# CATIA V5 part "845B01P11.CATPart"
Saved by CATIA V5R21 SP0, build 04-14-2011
Part number: 845B01P11
Bounding box of the stored display mesh (mm): x -51 to 51, y -25.54 to 25.54, z -6.5 to 6.5
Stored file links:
  C:\Users\ALI OZGUN\Desktop\alhan\845B01P11.CATPart
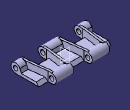
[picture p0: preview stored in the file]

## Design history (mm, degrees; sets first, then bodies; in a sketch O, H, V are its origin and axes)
Body1 (main body)
  Sketch1 on yz-plane, origin (0, 0, 0), H (0, 1, 0), V (0, 0, 1)
    construction line L1 (-19.05, 0) -> (19.05, 0)
    point P1 (-19.05, 0)
    point P2 (19.05, 0)
    line L2 (-19.05, 6.5) -> (19.05, 6.5)
    line L3 (19.05, -6.5) -> (-19.05, -6.5)
    arc A1 centre (19.05, 0) radius 6.5 from (19.05, 6.5) to (19.05, -6.5) cw
    arc A2 centre (-19.05, 0) radius 6.5 from (-19.05, -6.5) to (-19.05, 6.5) cw
    circle A3 centre (19.05, 0) radius 3.25
    circle A4 centre (-19.05, 0) radius 3.25
    distance L1 L2 = 6.5
    length L1 = 38.1
    distance P2 V = 19.05
    radius A3 = 3.25
    radius A4 = 3.25
    coincidence: P1 H
    horizontal: L1 H
    tangency: A1 L2, A2 L2, A1 L3, A2 L3
  Pad1: profile Sketch1, direction (1, 0, 0), length 51, mirrored extent
  Sketch2 on face of Pad1 from Sketch1.L2, origin (0, 0, 6.5), H (1, 0, 0), V (0, 1, 0)
    line L1 (12.5, -14) -> (38.5, -14)
    line L2 (38.5, -14) -> (38.5, -36.0786)
    line L3 (38.5, -36.0786) -> (12.5, -36.0786)
    line L4 (12.5, -36.0786) -> (12.5, -14)
    line L5 (-38.5, -14) -> (-12.5, -14)
    line L6 (-12.5, -14) -> (-12.5, -32.269)
    line L7 (-12.5, -32.269) -> (-38.5, -32.269)
    line L8 (-38.5, -32.269) -> (-38.5, -14)
    line L9 (60.2823, 31.3847) -> (38, 31.3847)
    line L10 (38, 31.3847) -> (38, 14)
    line L11 (38, 14) -> (60.2823, 14)
    line L12 (60.2823, 14) -> (60.2823, 31.3847)
    point P13 (-13, 31.3847)
    line L13 (-13, 31.3847) -> (13, 31.3847)
    line L14 (13, 31.3847) -> (13, 14)
    line L15 (13, 14) -> (-13, 14)
    line L16 (-13, 14) -> (-13, 31.3847)
    point P15 (13, 14)
    line L17 (-55.9786, 33.8185) -> (-38, 33.8185)
    line L18 (-38, 33.8185) -> (-38, 14)
    line L19 (-38, 14) -> (-55.9786, 14)
    line L20 (-55.9786, 14) -> (-55.9786, 33.8185)
    point P19 (-38, 14)
    reference projected line E1 (51, 19.05) -> (51, -19.05) from edge [face of Pad1 from Sketch1.L2 | end face of Pad1]
    reference projected line E2 (-51, 19.05) -> (-51, -19.05) from edge [start face of Pad1 | face of Pad1 from Sketch1.L2]
    reference projected line E3 (-51, 19.05) -> (-51, -19.05) from edge [start face of Pad1 | face of Pad1 from Sketch1.L2]
    reference projected line E4 (51, 19.05) -> (51, -19.05) from edge [face of Pad1 from Sketch1.L2 | end face of Pad1]
    reference projected line E5 through (0, 19.05) direction (1, 0) from axis of face of Pad1 from Sketch1.A1
    reference projected line E6 through (0, -19.05) direction (1, 0) from axis of face of Pad1 from Sketch1.A2
    distance L10 E1 = 13
    distance L18 E2 = 13
    distance L8 E3 = 12.5
    distance L2 E4 = 12.5
    distance L4 L2 = 26
    distance L8 L6 = 26
    distance L14 L10 = 25
    distance L16 L14 = 26
    distance L10 L12 = 22.2823
    distance L18 L20 = 17.9786
    distance L15 E5 = 5.05
    distance L1 E6 = 5.05
    horizontal: L1 H, L3 H, L5 H, L7 H, L9 H, L11 H, L13 H, L15 H, L17 H, L19 H
    vertical: L2 V, L4 V, L6 V, L8 V, L10 V, L12 V, L14 V, L16 V, L18 V, L20 V
    coincidence: P13 L9, P15 L11, P19 L11
  Pocket1: profile Sketch2, direction (0, 0, -1), length 53.5
  Sketch3 on end face of Pad1, origin (51, 0, 0), H (0, 1, 0), V (0, 0, 1)
    projected arc E1 centre (19.05, 0) radius 6.5 from (19.05, -6.5) to (19.05, 6.5) ccw from edge [face of Pocket1 from Sketch2.L10 | face of Pad1 from Sketch1.A1]
    projected arc E2 centre (19.05, 0) radius 6.5 from (19.05, -6.5) to (13.0358, 2.4657) ccw from edge [face of Pocket1 from Sketch2.L10 | face of Pad1 from Sketch1.A1]
    point P1 (19.05, -6.5)
    projected arc E3 centre (-19.05, 0) radius 6.5 from (-19.05, 6.5) to (-19.05, -6.5) ccw from edge [face of Pad1 from Sketch1.A2 | end face of Pad1]
    projected arc E4 centre (-19.05, 0) radius 6.5 from (-13.0358, 2.4657) to (-19.05, -6.5) ccw from edge [face of Pad1 from Sketch1.A2 | end face of Pad1]
    point P4 (-19.05, -6.5)
    projected line E5 (-19.05, -6.5) -> (14, -6.5) from edge [face of Pad1 from Sketch1.L3 | end face of Pad1]
    point P5 (-19.05, -6.5)
    projected line E6 (19.05, -6.5) -> (14, -6.5) from edge [face of Pocket1 from Sketch2.L10 | face of Pad1 from Sketch1.L3]
    point P7 (19.05, -6.5)
    line L1 (-13.0358, 2.4657) -> (-11, -2.5)
    line L2 (-11, -2.5) -> (11, -2.5)
    point P10 (11, -2.5)
    line L3 (11, -2.5) -> (13.0358, 2.4657)
    distance L2 E5 = 4
    length L2 = 22
    distance P10 V = 11
    horizontal: L2 H
    tangency: L3 E1, L1 E3
    coincidence: P1 P7, P4 P5
  Pocket2: profile Sketch3, direction (-1, 0, 0), length 172.5, outer side
  Sketch4 on face of Pocket2 from Sketch3.L2, origin (0, 0, -2.5), H (1, 0, 0), V (0, 1, 0)
    projected line E1 (12.5, -14) -> (12.5, -25.55) from edge [face of Pocket2 | face of Pocket1 from Sketch2.L4]
    projected line E2 (12.5, -14) -> (12.5, -19.05) from edge [face of Pocket2 | face of Pocket1 from Sketch2.L4]
    point P1 (12.5, -14)
    point P2 (12.5, -25.55)
    projected line E3 (38.5, -25.55) -> (38.5, -14) from edge [face of Pocket2 | face of Pocket1 from Sketch2.L2]
    projected line E4 (38.5, -19.05) -> (38.5, -14) from edge [face of Pocket2 | face of Pocket1 from Sketch2.L2]
    point P3 (38.5, -25.55)
    point P4 (38.5, -14)
    projected line E5 (13, 14) -> (13, 25.55) from edge [face of Pocket2 | face of Pocket1 from Sketch2.L14]
    projected line E6 (13, 14) -> (13, 19.05) from edge [face of Pocket2 | face of Pocket1 from Sketch2.L14]
    point P5 (13, 14)
    point P6 (13, 25.55)
    projected line E7 (38, 14) -> (38, 25.55) from edge [face of Pocket1 from Sketch2.L10 | face of Pocket2]
    projected line E8 (38, 14) -> (38, 19.05) from edge [face of Pocket1 from Sketch2.L10 | face of Pocket2]
    point P7 (38, 14)
    point P8 (38, 25.55)
    offset line E9 (9.5, -14) -> (9.5, -25.55) from edge [face of Pocket2 | face of Pocket1 from Sketch2.L4]
    offset line E10 (9.5, -14) -> (9.5, -19.05) from edge [face of Pocket2 | face of Pocket1 from Sketch2.L4]
    point P9 (9.5, -14)
    point P10 (9.5, -25.55)
    offset line E11 (16, 14) -> (16, 25.55) from edge [face of Pocket2 | face of Pocket1 from Sketch2.L14]
    offset line E12 (16, 14) -> (16, 19.05) from edge [face of Pocket2 | face of Pocket1 from Sketch2.L14]
    point P11 (16, 14)
    point P12 (16, 25.55)
    offset line E13 (35, 14) -> (35, 25.55) from edge [face of Pocket1 from Sketch2.L10 | face of Pocket2]
    offset line E14 (35, 14) -> (35, 19.05) from edge [face of Pocket1 from Sketch2.L10 | face of Pocket2]
    point P13 (35, 14)
    point P14 (35, 25.55)
    offset line E15 (41.5, -25.55) -> (41.5, -14) from edge [face of Pocket2 | face of Pocket1 from Sketch2.L2]
    offset line E16 (41.5, -19.05) -> (41.5, -14) from edge [face of Pocket2 | face of Pocket1 from Sketch2.L2]
    point P15 (41.5, -25.55)
    point P16 (41.5, -14)
    line L1 (9.5, -14) -> (13, 14)
    line L2 (12.5, -14) -> (16, 14)
    line L3 (38.5, -14) -> (35, 14)
    line L4 (41.5, -14) -> (38, 14)
    projected line E17 through (0, -19.05) direction (1, 0) from axis of face of Pocket2
    projected line E18 (38.5, -19.05) -> (41.5, -19.05) from axis of face of Pocket2
    projected line E19 (9.5, -19.05) -> (12.5, -19.05) from axis of face of Pocket2
    point P17 (-10000000, -19.05)
    point P18 (10000000, -19.05)
    point P19 (41.5, -19.05)
    point P20 (12.5, -19.05)
    point P21 (38.5, -19.05)
    point P22 (38.5, -19.05)
    point P23 (12.5, -19.05)
    point P24 (9.5, -19.05)
    point P25 (9.5, -19.05)
    projected line E20 through (0, 19.05) direction (1, 0) from axis of face of Pocket2
    projected line E21 (13, 19.05) -> (16, 19.05) from axis of face of Pocket2
    projected line E22 (35, 19.05) -> (38, 19.05) from axis of face of Pocket2
    point P26 (-10000000, 19.05)
    point P27 (10000000, 19.05)
    point P28 (38, 19.05)
    point P29 (13, 19.05)
    point P30 (13, 19.05)
    point P31 (16, 19.05)
    point P32 (35, 19.05)
    point P33 (16, 19.05)
    point P34 (35, 19.05)
    point P35 (-10000000, -19.05)
    point P36 (10000000, -19.05)
    point P37 (-10000000, 19.05)
    point P38 (10000000, 19.05)
    construction line L5 through (0, -19.05) direction (-1, 0)
    construction line L6 through (0, 19.05) direction (-1, 0)
    point P39 (-10000000, -19.05)
    point P40 (10000000, -19.05)
    point P41 (13, 14)
    point P42 (13, 25.55)
    point P43 (16, 14)
    point P44 (16, 25.55)
    point P45 (-10000000, 19.05)
    point P46 (10000000, 19.05)
    construction line L7 through (0, -19.05) direction (-1, 0)
    construction line L8 (13, 25.55) -> (13, 14)
    construction line L9 (16, 25.55) -> (16, 14)
    construction line L10 through (0, 19.05) direction (-1, 0)
    point P47 (-10000000, -19.05)
    point P48 (10000000, -19.05)
    point P49 (-10000000, 19.05)
    point P50 (10000000, 19.05)
    construction line L11 through (0, -19.05) direction (-1, 0)
    construction line L12 through (0, 19.05) direction (-1, 0)
    point P51 (-10000000, -19.05)
    point P52 (10000000, -19.05)
    point P53 (-41.5, -19.05)
    point P54 (-38.5, -19.05)
    point P55 (-12.5, -19.05)
    point P56 (-9.5, -19.05)
    point P57 (-13, 14)
    point P58 (-13, 25.55)
    construction line L13 (-13, 25.55) -> (-13, 14)
    point P59 (-16, 14)
    point P60 (-16, 25.55)
    construction line L14 (-16, 25.55) -> (-16, 14)
    point P61 (-12.5, -25.55)
    point P62 (-12.5, -14)
    point P63 (-12.5, -19.05)
    point P64 (-38.5, -14)
    point P65 (-38.5, -25.55)
    point P66 (-38.5, -19.05)
    point P67 (-13, 25.55)
    point P68 (-13, 14)
    point P69 (-13, 19.05)
    point P70 (-38, 25.55)
    point P71 (-38, 14)
    point P72 (-38, 19.05)
    point P73 (-9.5, -25.55)
    point P74 (-9.5, -14)
    point P75 (-9.5, -19.05)
    point P76 (-16, 25.55)
    point P77 (-16, 14)
    point P78 (-16, 19.05)
    point P79 (-35, 25.55)
    point P80 (-35, 14)
    point P81 (-35, 19.05)
    point P82 (-41.5, -14)
    point P83 (-41.5, -25.55)
    line L15 (-9.5, -14) -> (-13, 14)
    line L16 (-12.5, -14) -> (-16, 14)
    line L17 (-38.5, -14) -> (-35, 14)
    line L18 (-41.5, -14) -> (-38, 14)
    point P84 (-10000000, 19.05)
    point P85 (10000000, 19.05)
    point P86 (-16, 19.05)
    point P87 (-13, 19.05)
    point P88 (-35, 19.05)
    construction line L19 through (0, -19.05) direction (-1, 0)
    line L20 (-38.5, -19.05) -> (-41.5, -19.05)
    line L21 (-9.5, -19.05) -> (-12.5, -19.05)
    construction line L22 (-12.5, -14) -> (-12.5, -25.55)
    line L23 (-12.5, -14) -> (-12.5, -19.05)
    construction line L24 (-38.5, -25.55) -> (-38.5, -14)
    line L25 (-38.5, -19.05) -> (-38.5, -14)
    construction line L26 (-13, 14) -> (-13, 25.55)
    line L27 (-13, 14) -> (-13, 19.05)
    construction line L28 (-38, 14) -> (-38, 25.55)
    line L29 (-38, 14) -> (-38, 19.05)
    construction line L30 (-9.5, -14) -> (-9.5, -25.55)
    line L31 (-9.5, -14) -> (-9.5, -19.05)
    construction line L32 (-16, 14) -> (-16, 25.55)
    line L33 (-16, 14) -> (-16, 19.05)
    construction line L34 (-35, 14) -> (-35, 25.55)
    line L35 (-35, 14) -> (-35, 19.05)
    construction line L36 (-41.5, -25.55) -> (-41.5, -14)
    line L37 (-41.5, -19.05) -> (-41.5, -14)
    construction line L38 through (0, 19.05) direction (-1, 0)
    line L39 (-13, 19.05) -> (-16, 19.05)
    line L40 (-35, 19.05) -> (-38, 19.05)
    parallelism: L2 L1
    coincidence: E1 P20, E3 P21, E17 P22, E17 P23, E17 P24, E9 P25, E5 P29, E20 P30, E20 P31, E20 P32, E11 P33, E13 P34, P21 P22, P24 P25, P29 P30, P31 P33, P32 P34
    symmetry: P18 P35 V, P17 P36 V, E17 L5 V, P27 P37 V, P26 P38 V, E20 L6 V, P18 P39 V, P17 P40 V, E17 L7 V, P27 P45 V, P26 P46 V, E20 L10 V, P18 P47 V, P17 P48 V, E17 L11 V, P27 P49 V, P26 P50 V, E20 L12 V, P18 P51 V, P17 P52 V, P19 P53 V, P21 P54 V, P20 P55 V, P25 P56 V, E17 L19 V, P41 P57 V, P42 P58 V, L8 L13 V, P43 P59 V, P44 P60 V, L9 L14 V, P2 P61 V, P1 P62 V, P23 P63 V, E1 L22 V, P4 P64 V, P3 P65 V, P22 P66 V, E3 L24 V, P6 P67 V, P5 P68 V, P30 P69 V, E5 L26 V, P8 P70 V, P7 P71 V, P28 P72 V, E7 L28 V, P10 P73 V, P9 P74 V, P24 P75 V, E9 L30 V, P12 P76 V, P11 P77 V, P31 P78 V, E11 L32 V, P14 P79 V, P13 P80 V, P32 P81 V, E13 L34 V, P16 P82 V, P15 P83 V, E15 L36 V, L1 L15 V, L2 L16 V, L3 L17 V, L4 L18 V, P27 P84 V, P26 P85 V, P33 P86 V, P29 P87 V, P34 P88 V, E20 L38 V, E17 L21 V, E17 L20 V, E1 L23 V, E3 L25 V, E5 L27 V, E7 L29 V, E9 L31 V, E11 L33 V, E13 L35 V, E15 L37 V, E20 L40 V, E20 L39 V
  Pad2: profile Sketch4, direction (0, 0, 1), length 9
  Sketch5 on yz-plane, origin (0, 0, 0), H (0, 1, 0), V (0, 0, 1)
    projected circle E1 centre (-19.05, 0) radius 3.25 from edge [end face of Pad1 | face of Pad1 from Sketch1.A4]
    circle A1 centre (19.05, 0) radius 3.25
    reference projected circle E2 centre (19.05, 0) radius 3.25 from edge [face of Pad1 from Sketch1.A3 | face of Pad2]
    coincidence: A1 E2
  Pocket3: profile Sketch5, direction (-1, 0, 0), length 95, mirrored extent
  RemoveFace1: RemoveFaces (face of Pocket2 from Sketch3.L3; face of Pocket2; face of Pocket2 from Sketch3.L3; face of Pocket2; face of Pocket2 from Sketch3.L1; face of Pocket2; face of Pocket2; face of Pocket2; face of Pocket2 from Sketch3.L3; face of Pocket2 from Sketch3.L1)
  Chamfer1: length 4, angle 45, on edge [face of Pocket1 from Sketch2.L19 | face of Pocket2 from Sketch3.L2]; edge [face of Pocket1 from Sketch2.L5 | face of Pocket2 from Sketch3.L2]; edge [face of Pocket1 from Sketch2.L15 | face of Pocket2 from Sketch3.L2]; edge [face of Pocket1 from Sketch2.L1 | face of Pocket2 from Sketch3.L2]; edge [face of Pocket1 from Sketch2.L11 | face of Pocket2 from Sketch3.L2]
Body2
  Solid1: linked copy from another document
  Translate1: Direction zx-plane, Length 38.1, ToTransfor Solid1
